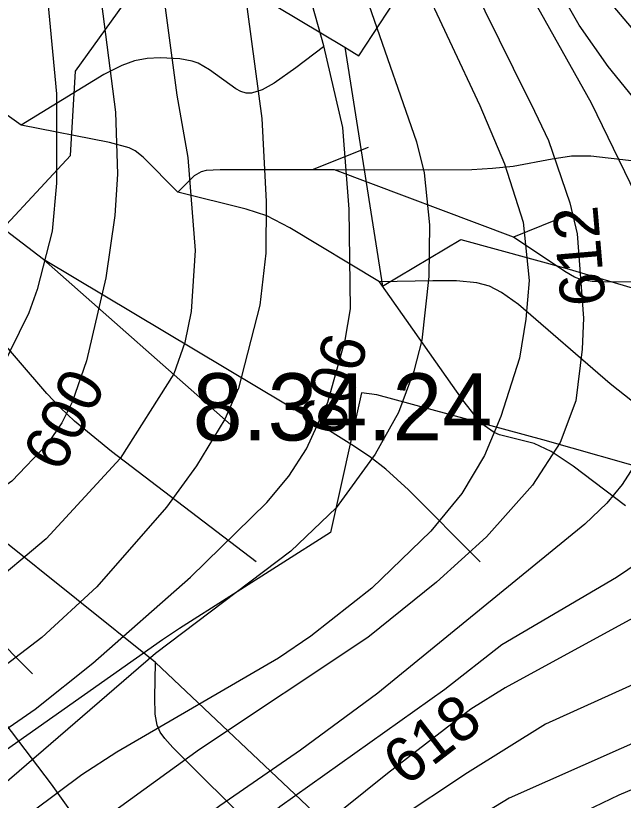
# Model space of a CAD drawing. Extents: x -709584 to -702006, y -1161789 to -1157496.
# Drawn here: x -708748.2 to -708612.5, y -1161517.8 to -1161342.6 of the extents above; entities that cross this region are included whole.
import ezdxf

# ---------------------------------------------------------------- set-up
doc = ezdxf.new("R2010")
doc.units = 0
for name, color, linetype in [('103_hranice KÚ', 7, 'Continuous'), ('120_vrstevnice hlavní', 7, 'Continuous'), ('121_vrstevnice hlavní_popis', 7, 'Continuous'), ('122_vrstevnice základní', 7, 'Continuous'), ('408_BPEJ_linie', 7, 'Continuous'), ('409_BPEJ_popis', 7, 'Continuous'), ('411_akumulovaný odtok', 7, 'Continuous')]:
    doc.layers.add(name, color=color, linetype=linetype)

msp = doc.modelspace()

# ---------------------------------------------------------------- linework, layer by layer
at = {"layer": '103_hranice KÚ'}
msp.add_lwpolyline([(-708920.55, -1161485.93), (-708896.6, -1161465.8), (-708869.55, -1161443.21), (-708843.36, -1161441.03), (-708804.47, -1161428.27), (-708758.03, -1161397.48), (-708735.99, -1161373.78), (-708734.84, -1161354.97), (-708718.77, -1161332.55), (-708710.35, -1161328.22), (-708674.72, -1161349.64), (-708671.55, -1161351.55), (-708632.49, -1161291.91), (-708615.92, -1161270.42), (-708597.31, -1161247.69)], dxfattribs=at)
at = {"layer": '120_vrstevnice hlavní'}
for points in [[(-708689.54, -1161164.31), (-708704.1, -1161195.14), (-708706.85, -1161202.23), (-708712.2, -1161223.2), (-708721.89, -1161258.79), (-708727.39, -1161280.48), (-708729.56, -1161293.5), (-708730.14, -1161323.88), (-708729.41, -1161336.89), (-708725.94, -1161364.09), (-708725.51, -1161377.97), (-708726.09, -1161387.23), (-708728.11, -1161401.12), (-708732.45, -1161419.63), (-708735.63, -1161428.89), (-708737.95, -1161433.52), (-708741.13, -1161438.15)], [(-708664.9, -1161319.25), (-708644.51, -1161362.64), (-708639.01, -1161375.66), (-708634.82, -1161388.68), (-708633.51, -1161401.69), (-708634.24, -1161410.37), (-708635.68, -1161419.05), (-708639.88, -1161432.07), (-708643.49, -1161440.75), (-708648.56, -1161449.28), (-708655.5, -1161457.67), (-708668.66, -1161470.4), (-708682.26, -1161481.1), (-708689.49, -1161486.02), (-708725.65, -1161507), (-708733.46, -1161512.06), (-708744.31, -1161520.16)], [(-708741.13, -1161438.15), (-708749.08, -1161446.53), (-708762.1, -1161455.65), (-708782.35, -1161467.8), (-708806.65, -1161480.24), (-708830.95, -1161488.05), (-708839.05, -1161489.35), (-708847.15, -1161489.93), (-708859.3, -1161489.49), (-708883.89, -1161485.15), (-708896.91, -1161487.18), (-708905.59, -1161490.51)], [(-708590.84, -1161483.13), (-708629.9, -1161500.78), (-708647.26, -1161511.62), (-708663.46, -1161522.33)]]:
    msp.add_lwpolyline(points, dxfattribs=at)
at = {"layer": '122_vrstevnice základní'}
for points in [[(-708547.16, -1161104.16), (-708617.53, -1161187.05), (-708627.87, -1161202.08), (-708633.22, -1161210.76), (-708640.31, -1161225.23), (-708645.95, -1161239.69), (-708651.45, -1161257.05), (-708653.04, -1161265.73), (-708653.76, -1161274.41), (-708653.33, -1161285.4), (-708651.88, -1161293.21), (-708647.83, -1161306.23), (-708638.29, -1161328.79), (-708619.63, -1161362.06), (-708607.33, -1161387.52)], [(-708625.56, -1161113.71), (-708667.8, -1161172.87), (-708684.86, -1161205.27), (-708693.83, -1161226.1), (-708698.32, -1161239.98), (-708700.63, -1161250.98), (-708702.8, -1161267.18), (-708703.23, -1161285.4), (-708702.22, -1161307.68), (-708697.16, -1161336.03), (-708693.25, -1161365.53), (-708692.24, -1161384.05), (-708692.38, -1161395.62), (-708693.69, -1161407.19), (-708698.46, -1161425.71), (-708701.5, -1161432.65), (-708707.86, -1161443.06), (-708714.52, -1161452.32), (-708730.14, -1161470.11), (-708742.43, -1161481.39), (-708750.68, -1161487.76), (-708792.02, -1161511.98)], [(-708581.73, -1161412.69), (-708584.91, -1161398.8), (-708587.52, -1161391.86), (-708592.58, -1161382.6), (-708615.87, -1161353.96), (-708622.38, -1161344.7), (-708633.8, -1161324.6), (-708637.85, -1161315.49), (-708642.05, -1161303.92), (-708644.8, -1161292.34), (-708645.66, -1161285.4), (-708645.95, -1161269.2), (-708644.94, -1161257.63), (-708641.61, -1161243.74), (-708637.71, -1161234.49), (-708634.09, -1161227.54), (-708620.64, -1161206.71), (-708604.58, -1161183.86), (-708588.53, -1161166.5)], [(-708705.55, -1161169.4), (-708714.66, -1161187.62), (-708722.04, -1161205.85), (-708724.78, -1161214.24), (-708733.9, -1161248.95), (-708736.36, -1161260.52), (-708738.09, -1161272.09), (-708740.84, -1161298.13), (-708742, -1161317.51), (-708741.56, -1161334), (-708739.1, -1161360.04), (-708739.1, -1161380), (-708740.12, -1161390.7), (-708743.44, -1161403.72), (-708745.32, -1161408.93), (-708751.69, -1161421.94), (-708759.07, -1161432.94), (-708764.13, -1161438.72), (-708771.65, -1161444.94), (-708790.16, -1161456.8), (-708806.36, -1161465.92), (-708820.25, -1161472.14)], [(-708782.64, -1161523.2), (-708771.79, -1161516.69), (-708743.88, -1161497.45), (-708731, -1161487.18), (-708709.16, -1161467.94), (-708692.09, -1161451.31), (-708687.18, -1161445.38), (-708683.27, -1161439.3), (-708678.5, -1161428.89), (-708674.59, -1161415), (-708673.44, -1161408.06), (-708673.73, -1161385.78), (-708675.17, -1161367.56), (-708679.37, -1161349.33), (-708688.48, -1161316.93), (-708691.23, -1161304.78), (-708693.11, -1161292.63), (-708693.54, -1161276.43), (-708692.82, -1161262.26), (-708689.35, -1161242.01), (-708681.68, -1161219.73), (-708667.36, -1161191.38)], [(-708599.81, -1161194.27), (-708613.12, -1161209.75), (-708621.22, -1161220.6), (-708630.77, -1161237.09), (-708634.53, -1161246.64), (-708636.84, -1161256.18), (-708638.43, -1161268.91), (-708638.29, -1161284.82), (-708636.55, -1161297.55), (-708631.92, -1161313.46), (-708627.58, -1161323.01), (-708621.36, -1161332.55), (-708609.94, -1161346.15)], [(-708655.64, -1161236.22), (-708658.68, -1161250.11), (-708661, -1161266.31), (-708661, -1161280.19), (-708659.55, -1161291.76), (-708655.64, -1161310.28), (-708652.32, -1161321.85), (-708649.71, -1161328.79), (-708633.95, -1161360.61), (-708633.08, -1161362.35), (-708629.17, -1161370.45), (-708624.4, -1161384.34), (-708622.81, -1161391.28), (-708621.36, -1161410.08), (-708621.65, -1161417.03), (-708623.1, -1161428.6), (-708626.57, -1161437.86), (-708632.79, -1161447.4), (-708643.06, -1161458.97), (-708654.2, -1161469.1), (-708669.53, -1161481.39), (-708707.14, -1161506.42), (-708745.32, -1161534.04)], [(-708715.38, -1161265.44), (-708717.41, -1161277.01), (-708718.57, -1161290.9), (-708718.57, -1161302.47), (-708716.54, -1161327.93), (-708712.2, -1161360.33), (-708709.74, -1161374.21), (-708708.15, -1161395.04), (-708709.02, -1161408.64), (-708710.46, -1161415.58), (-708712.92, -1161422.52), (-708724.93, -1161441.47), (-708741.42, -1161459.41), (-708755.16, -1161470.83), (-708784.38, -1161490.51), (-708799.13, -1161497.45), (-708809.55, -1161500.34), (-708830.38, -1161504.25), (-708837.61, -1161505.11), (-708866.83, -1161504.39), (-708879.84, -1161505.55), (-708892.72, -1161508.88), (-708900.24, -1161511.62), (-708904.87, -1161514.52)], [(-708678.79, -1161312.88), (-708658.68, -1161370.74), (-708656.95, -1161377.68), (-708655.79, -1161389.26), (-708655.93, -1161400.83), (-708657.53, -1161415), (-708659.26, -1161421.94), (-708662.73, -1161431.2), (-708667.94, -1161440.46), (-708676.62, -1161452.46), (-708686.74, -1161462.16), (-708716.97, -1161485.01), (-708751.25, -1161514.52), (-708768.76, -1161528.84), (-708780.62, -1161536.5), (-708790.74, -1161540.41), (-708800.87, -1161542.72), (-708857.57, -1161551.54), (-708867.69, -1161554.73), (-708875.79, -1161558.92), (-708883.89, -1161563.99), (-708903.57, -1161581.92)], [(-708884.64, -1161641), (-708876.95, -1161638.19), (-708870.01, -1161636.31), (-708844.55, -1161631.1), (-708830.66, -1161627.34), (-708808.97, -1161619.53), (-708791.9, -1161611.72), (-708781.2, -1161604.63), (-708773.39, -1161598.41), (-708752.84, -1161577.44), (-708722.76, -1161548.51), (-708689.2, -1161519.15), (-708652.32, -1161492.96), (-708639.59, -1161482.98), (-708613.99, -1161467.94), (-708601.11, -1161459.26), (-708590.99, -1161449.72), (-708586.21, -1161443.35), (-708584.05, -1161439.45), (-708581.88, -1161433.52), (-708580.86, -1161424.26), (-708581.73, -1161412.69)], [(-708527.78, -1161430.62), (-708530.38, -1161446.82), (-708532.55, -1161456.08), (-708537.33, -1161469.97), (-708542.97, -1161479.37), (-708546.44, -1161482.84), (-708550.78, -1161485.73), (-708558.44, -1161488.92), (-708576.67, -1161492.1), (-708596.48, -1161498.9), (-708638, -1161517.27), (-708653.62, -1161526.81), (-708657.81, -1161530.43), (-708662.3, -1161533.32), (-708671.56, -1161541.42), (-708675.89, -1161545.33), (-708705.4, -1161569.63), (-708714.66, -1161578.02), (-708729.7, -1161594.65), (-708750.68, -1161622.42), (-708765.57, -1161639.34), (-708767.3, -1161641.01)], [(-708608.18, -1161440.16), (-708612.71, -1161447.26), (-708616.16, -1161451.45), (-708621.07, -1161456.08), (-708667.36, -1161493.83), (-708684.57, -1161506.56), (-708702.65, -1161519), (-708721.31, -1161533.18), (-708737.51, -1161547.5), (-708763.41, -1161574.4), (-708777.15, -1161585.39), (-708791.03, -1161594.07), (-708801.45, -1161599.42), (-708808.39, -1161602.03), (-708822.28, -1161605.79), (-708832.69, -1161607.23), (-708855.25, -1161608.1), (-708863.93, -1161609.98), (-708872.61, -1161613.31), (-708905.45, -1161633.12), (-708925.53, -1161641)], [(-708607.91, -1161475.75), (-708638.87, -1161492.68), (-708646.53, -1161497.45), (-708665.19, -1161511.77), (-708703.38, -1161542.43), (-708720.3, -1161557.48), (-708739.39, -1161578.45), (-708746.77, -1161587.42), (-708770.06, -1161611.86), (-708782.93, -1161623.58), (-708795.08, -1161631.53), (-708810.7, -1161639.63), (-708814.23, -1161641)], [(-708624.55, -1161521.89), (-708613.41, -1161516.54), (-708596.63, -1161509.45)]]:
    msp.add_lwpolyline(points, dxfattribs=at)
at = {"layer": '408_BPEJ_linie'}
for points in [[(-708829.49, -1161460.04), (-708785.08, -1161442.88), (-708777.17, -1161432.88), (-708758.03, -1161397.48), (-708735.99, -1161373.78), (-708734.84, -1161354.97), (-708718.77, -1161332.55), (-708710.35, -1161328.22), (-708674.72, -1161349.64), (-708666.3, -1161402.95), (-708648.75, -1161392.55), (-708625.07, -1161399.03), (-708595.13, -1161407.9)], [(-708604.79, -1161444.56), (-708630.44, -1161437.29), (-708667.52, -1161427.27), (-708670.96, -1161426.82), (-708677.9, -1161457.99), (-708711.62, -1161479.44), (-708715.43, -1161481.91), (-708757.42, -1161511.46), (-708788.76, -1161534.58), (-708822.71, -1161554.32), (-708843.92, -1161465.04), (-708829.49, -1161460.04)]]:
    msp.add_lwpolyline(points, dxfattribs=at)
at = {"layer": '411_akumulovaný odtok'}
for p, q in [((-708669.49, -1161372), (-708681.99, -1161377)), ((-708676.99, -1161377), (-708681.99, -1161377)), ((-708636.99, -1161392), (-708676.99, -1161377)), ((-708624.49, -1161387), (-708636.99, -1161392)), ((-708699.49, -1161434.5), (-708741.99, -1161397)), ((-708716.99, -1161487), (-708766.99, -1161447))]:
    msp.add_line(p, q, dxfattribs=at)
for points in [[(-708746.99, -1161367), (-708761.2, -1161356.9), (-708772.76, -1161349.14), (-708779.34, -1161345.18), (-708790.43, -1161339.42), (-708793.12, -1161337.59), (-708800.86, -1161331.57), (-708803.57, -1161329.75), (-708814.63, -1161323.87), (-708820.45, -1161320.2), (-708826.2, -1161316.18), (-708834.67, -1161309.77), (-708842.94, -1161303.07), (-708851.09, -1161296.2), (-708856.42, -1161291.51), (-708861.6, -1161286.66), (-708866.53, -1161281.58), (-708871.85, -1161275.67), (-708891.99, -1161252)], [(-708574.49, -1161344.5), (-708580.37, -1161353.02), (-708583.8, -1161357.61), (-708587.29, -1161361.72), (-708589.02, -1161363.44), (-708592.43, -1161366.4), (-708597.8, -1161370.39), (-708601.5, -1161372.65), (-708605.3, -1161374.33), (-708607.27, -1161374.81), (-708609.28, -1161374.98), (-708611.33, -1161374.92), (-708619.76, -1161373.95), (-708624.05, -1161373.98), (-708628.35, -1161374.59), (-708637.06, -1161376.23), (-708641.69, -1161376.72), (-708646.36, -1161376.96), (-708656, -1161377.09), (-708676.99, -1161377)], [(-708679.49, -1161349.5), (-708685.66, -1161354.23), (-708690.52, -1161357.67), (-708693.17, -1161359.14), (-708695.57, -1161359.85), (-708696.75, -1161359.85), (-708697.92, -1161359.52), (-708699.08, -1161358.94), (-708704.92, -1161354.65), (-708707.48, -1161353.2), (-708708.8, -1161352.74), (-708711.58, -1161352.18), (-708715.93, -1161351.96), (-708718.85, -1161352.13), (-708721.7, -1161352.66), (-708724.51, -1161353.67), (-708728.56, -1161355.73), (-708746.99, -1161367)], [(-708711.99, -1161382), (-708719.74, -1161374.18), (-708721.54, -1161372.77), (-708722.86, -1161372.07), (-708727.26, -1161370.88), (-708746.99, -1161367)], [(-708681.99, -1161377), (-708702.52, -1161376.96), (-708705.65, -1161377.13), (-708706.81, -1161377.42), (-708708.35, -1161378.37), (-708711.99, -1161382)], [(-708741.99, -1161397), (-708757.68, -1161385.1), (-708759.86, -1161383.67), (-708762.13, -1161382.73), (-708763.76, -1161382.63), (-708766.31, -1161382.98), (-708781.99, -1161387)], [(-708666.99, -1161402), (-708686.97, -1161389.97), (-708692.09, -1161387.26), (-708696.73, -1161385.77), (-708711.99, -1161382)], [(-708694.49, -1161464.5), (-708726.84, -1161439.86), (-708735.11, -1161433.12), (-708738.24, -1161430.15), (-708741.25, -1161426.97), (-708759.88, -1161405.38), (-708763.36, -1161401.74), (-708767.6, -1161397.94), (-708769.81, -1161396.24), (-708773.31, -1161393.94), (-708776.99, -1161392)], [(-708596.99, -1161402), (-708617.01, -1161402.07), (-708619.47, -1161401.96), (-708621.85, -1161401.55), (-708623.38, -1161400.94), (-708625.58, -1161399.7), (-708636.99, -1161392)], [(-708644.49, -1161464.5), (-708660.48, -1161448.41), (-708665.56, -1161443.84), (-708669.2, -1161441.03), (-708673.1, -1161438.4), (-708681.13, -1161433.44), (-708741.99, -1161397)], [(-708596.99, -1161432), (-708598.97, -1161432.05), (-708601.84, -1161431.85), (-708605.21, -1161431.18), (-708607.08, -1161430.52), (-708610.43, -1161428.75), (-708615.44, -1161424.79), (-708635.92, -1161407.1), (-708639.68, -1161404.36), (-708642.35, -1161402.98), (-708645.19, -1161402.23), (-708649.72, -1161401.8), (-708655.05, -1161401.76), (-708666.99, -1161402)], [(-708611.99, -1161452), (-708623.72, -1161443.14), (-708628.59, -1161439.92), (-708632.41, -1161438.13), (-708640.16, -1161436.2), (-708641.33, -1161435.68), (-708643.56, -1161434.05), (-708645.55, -1161431.95), (-708648.32, -1161428.39), (-708666.99, -1161402)], [(-708744.49, -1161489.5), (-708754.25, -1161479.81), (-708756.1, -1161477.58), (-708757.08, -1161475.97), (-708759.16, -1161470.68), (-708766.99, -1161447)], [(-708704.49, -1161564.5), (-708711.32, -1161557.83), (-708716.06, -1161552.95), (-708720.53, -1161547.89), (-708722.37, -1161545.53), (-708723.8, -1161543.36), (-708724.99, -1161541.19), (-708728.45, -1161532.48), (-708729.6, -1161530.1), (-708732.33, -1161525.46), (-708735.37, -1161520.91), (-708740.22, -1161514.18), (-708753.69, -1161496.51), (-708759.06, -1161490.19), (-708764.71, -1161484.19), (-708791.99, -1161457)], [(-708694.49, -1161524.5), (-708713.1, -1161506.01), (-708714.94, -1161503.97), (-708715.97, -1161502.52), (-708716.65, -1161500.98), (-708717.06, -1161498.5), (-708717.15, -1161494.83), (-708716.99, -1161487)], [(-708626.99, -1161579.5), (-708626.88, -1161579.01), (-708627.07, -1161577.82), (-708627.62, -1161576.1), (-708628.63, -1161573.96), (-708630.06, -1161571.57), (-708633.83, -1161566.48), (-708638.08, -1161561.67), (-708643.84, -1161556.06), (-708716.99, -1161487)]]:
    msp.add_lwpolyline(points, dxfattribs=at)

# ---------------------------------------------------------------- texts
at = {"layer": '121_vrstevnice hlavní_popis'}
for s, rotation, p in [('612', 94.9191, (-708616.39, -1161406.99)), ('606', 74.2441, (-708675.45, -1161436.97)), ('600', 62.4643, (-708738.19, -1161444.89)), ('618', 37.5878, (-708661.11, -1161514.87))]:
    msp.add_text(s, height=10, rotation=rotation, dxfattribs=at).set_placement(p)
at = {"layer": '409_BPEJ_popis'}
msp.add_text('8.34.24', height=15, dxfattribs=at).set_placement((-708708.69, -1161437.43))

doc.saveas('drawing.dxf')
